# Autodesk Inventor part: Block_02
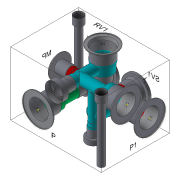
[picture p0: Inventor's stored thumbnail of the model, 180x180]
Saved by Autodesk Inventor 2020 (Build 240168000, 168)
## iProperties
Created: 2020-04
Part Number: Block_02
Material: Generico
Document SubType Name: Modeling
Designer: carlo
Density: 1 g/cm^3
Appearance: Default
DataBaseUnit: MM
VESTPrecisionDepth: 0
ActiveCavityLibraryName: *All Libraries*
VESTEnergyEfficiencyOptions: <?xml version="1.0"?> <DesignSettings xmlns:xsd="http://www.w3.org/2001/XMLSchema" xmlns:xsi="http://www.w3.org/2001/XMLSchema-instance"> <ImperialNetOptions> <
VESTUseStandardDiameter: True
VESTPrecisionLocation: 0
VESTPrecisionAngle: 0
BreakTolerance: 1,5
Author: carlo
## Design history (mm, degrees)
sketch "Schizzo1"
  geometry: L1 (0, 0)-(100, 0) reference; L2 (100, 0)-(100, -70); L3 (100, -70)-(0, -70); L4 (0, -70)-(0, 0) reference
  constraints: 8 end point, 2 horizontal, 2 parallel, 1 perpendicular, 1 vertical
  dimensions: "BlockLength" = 100 distance of L1.start L1.end; "BlockHeight" = 70 distance of L1.end L2.end
extrude "Estrusione1" join sketch "Schizzo1" distance "BlockWidth" = 75; taper "BlockTaperAngle" = 0 deg
sketch "Schizzo2"
  geometry: 1 further point
sketch "Schizzo3"
  geometry: L1 (0, 0)-(7.556, 0); L2 (0, 0)-(0, 7.556); L3 (0, 0)-(15.11, 0) reference; L4 (0, 0)-(7.556, 0); L5 (-50, 45)-(90, 45) reference
  constraints: 8 end point, 1 horizontal, 1 parallel, 1 perpendicular
  dimensions: "d6" = 0 dimension on L1.start L1.end L3.end; "d7" = 0 dimension on L1.start L4.end L3.end
revolve "P-Port" stored, may be unused: angle "d23" = 0 deg
sketch "Schizzo5"
  geometry: 1 further point
sketch "Schizzo6"
  geometry: L1 (0, 0)-(6.667, 0); L2 (0, 0)-(0, 6.667); L3 (0, 0)-(13.332, 0) reference; L4 (0, 0)-(6.667, 0); L5 (-68, -53.7)-(72, -53.7) reference
  constraints: 8 end point, 1 horizontal, 1 parallel, 1 perpendicular
  dimensions: "d26" = 0 dimension on L1.start L1.end L3.end; "d27" = 0 dimension on L1.start L4.end L3.end
revolve "RV1-CV" stored, may be unused: angle "d51" = 0 deg
sketch "Schizzo8"
  geometry: 1 further point
sketch "Schizzo9"
  geometry: L1 (0, 0)-(7.556, 0); L2 (0, 0)-(0, 7.556); L3 (0, 0)-(15.11, 0) reference; L4 (0, 0)-(7.556, 0); L5 (62, 19.31)-(-43, 19.31) reference
  constraints: 8 end point, 1 horizontal, 1 parallel, 1 perpendicular
  dimensions: "d54" = 0 dimension on L1.start L1.end L3.end; "d55" = 0 dimension on L1.start L4.end L3.end
revolve "T-Port" stored, may be unused: angle "d71" = 0 deg
sketch "Schizzo11"
  geometry: 1 further point
sketch "Schizzo12"
  geometry: L1 (0, 0)-(6.667, 0); L2 (0, 0)-(0, 6.667); L3 (0, 0)-(13.332, 0) reference; L4 (0, 0)-(6.667, 0); L5 (85, 45)-(-55, 45) reference
  constraints: 8 end point, 1 horizontal, 1 parallel, 1 perpendicular
  dimensions: "d74" = 0 dimension on L1.start L1.end L3.end; "d75" = 0 dimension on L1.start L4.end L3.end
revolve "SV1-CV" stored, may be unused: angle "d99" = 0 deg
node "Schizzo14"
sketch "Schizzo15"
  geometry: 1 further point
sketch "Schizzo16"
  geometry: L1 (0, 0)-(3.333, 0); L2 (0, 0)-(0, 3.333); L3 (0, 0)-(6.666, 0) reference; L4 (0, 0)-(3.333, 0); L5 (-85, 26)-(55, 26) reference
  constraints: 8 end point, 1 horizontal, 1 parallel, 1 perpendicular
  dimensions: "d102" = 0 dimension on L1.start L1.end L3.end; "d103" = 0 dimension on L1.start L4.end L3.end
revolve "PLUG1-Port" stored, may be unused: angle "d119" = 0 deg
node "Schizzo18"
sketch "Schizzo19"
  geometry: 1 further point
sketch "Schizzo22"
  geometry: L1 (0, 0)-(5.556, 0); L2 (0, 0)-(0, 5.556); L3 (0, 0)-(11.11, 0) reference; L4 (0, 0)-(5.556, 0); L5 (-36.3, 45)-(68.7, 45) reference
  constraints: 8 end point, 1 horizontal, 1 parallel, 1 perpendicular
  dimensions: "d142" = 0 dimension on L1.start L1.end L3.end; "d143" = 0 dimension on L1.start L4.end L3.end
revolve "MP-Port" stored, may be unused: angle "d159" = 0 deg
sketch "Schizzo24"
  geometry: 1 further point
hole "mh1-BH" sketch "Schizzo24" at (7, 68) diameter "d161" = 7; stored, may be unused: countersink angle "d165" = 90 deg, drill point angle "d167" = 120 deg; dims "d162" = 6, "d163" = 10.5, "d164" = 8, "d166" = 70
sketch "Schizzo25"
  geometry: 1 further point
hole "mh2-BH" sketch "Schizzo25" at (93, 7) diameter "d169" = 7; stored, may be unused: countersink angle "d173" = 90 deg, drill point angle "d175" = 120 deg; dims "d170" = 6, "d171" = 10.5, "d172" = 8, "d174" = 70
sketch "Schizzo26"
  geometry: 2 further points
  constraints: 1 other
  dimensions: "d282" = 23.66923 horizontal distance of point (48, 53.7) point (24.331, 65.992) (derived); "d283" = 12.29198 vertical distance of point (48, 53.7) point (24.331, 65.992) (derived)
sketch "Schizzo27"
  geometry: 2 further points
  constraints: 1 other
  dimensions: "d178" = 15 horizontal distance of point (30, -45) point (45, -64) (derived); "d179" = 19 vertical distance of point (30, -45) point (45, -64) (derived)
sketch "Schizzo28"
  geometry: 2 further points
  constraints: 1 other
  dimensions: "d180" = 18 horizontal distance of point (28, -19.31) point (46, -9) (derived); "d181" = 10.31 vertical distance of point (28, -19.31) point (46, -9) (derived)
sketch "Schizzo29"
  geometry: 2 further points
  constraints: 1 other
  dimensions: "d288" = 24.10718 horizontal distance of point (-65, -45) point (-89.107, -27.281) (derived); "d289" = 17.71872 vertical distance of point (-65, -45) point (-89.107, -27.281) (derived)
sketch "Schizzo30"
  geometry: 2 further points
  constraints: 1 other
  dimensions: "d184" = 8.7 horizontal distance of point (-53.7, -45) point (-45, -30) (derived); "d185" = 15 vertical distance of point (-53.7, -45) point (-45, -30) (derived)
sketch "Schizzo31"
  geometry: 1 further point
sketch "Schizzo32"
  geometry: L1 (0, 0)-(7.556, 0); L2 (0, 0)-(0, 7.556); L3 (0, 0)-(15.11, 0) reference; L4 (0, 0)-(7.556, 0); L5 (36.3, 45)-(-68.7, 45) reference
  constraints: 8 end point, 1 horizontal, 1 parallel, 1 perpendicular
  dimensions: "d188" = 0 dimension on L1.start L1.end L3.end; "d189" = 0 dimension on L1.start L4.end L3.end
sketch "Schizzo33"
  geometry: L1 (0, 0)-(0, 4.25); L2 (0, 4.25)-(17, 4.25); L3 (17, 4.25)-(17, 0); L4 (17, 0)-(0, 0); L5 (17, 0)-(17, -1); L6 (17, -1)-(0, -1); L7 (17, -1)-(10.5, -1); L8 (10.5, -1)-(10.5, -15.001); L9 (10.5, -15.001)-(10.5, -16); L10 (10.5, -16)-(9.55, -16); L11 (9.55, -16)-(9.55, -21); L12 (9.55, -21)-(5.5, -23.433); L13 (5.5, -23.433)-(5.5, -36); L14 (5.5, -36)-(0, -39.305); L15 (0, -39.305)-(0, 4.25)
  constraints: 30 end point, 7 parallel, 2 collinear, 1 perpendicular, 1 vertical
  dimensions: "d191" = 4.25 distance of L1.start L1.end (computed from d192, d190); "d192" = 17 distance of L1.end L2.end; "d193" = 1 distance of L3.end L5.end; "d194" = 90 deg angle of L1 L7; "d195" = 14.001 distance from line of L6 L8.end (computed from d196, d193, d197, d192, d194); "d196" = 15 distance from line of L6 L9.end; "d197" = 10.5 distance from line of L1 L9.end; "d198" = 90 deg angle of L1 L10; "d199" = 20 distance from line of L6 L11.end; "d200" = 9.55 distance from line of L1 L11.end; "d201" = 59 deg angle of L1 L12; "d202" = 36 distance from line of L4 L13.end; "d203" = 5.5 distance from line of L1 L13.end; "d204" = 59 deg angle of L1 L14
revolve "P1-Port" sketch "Schizzo33" stored, may be unused: angle "d205" = 0 deg
sketch "Schizzo38"
  geometry: 1 further point
sketch "Schizzo39"
  geometry: L1 (0, 0)-(6.667, 0); L2 (0, 0)-(0, 6.667); L3 (0, 0)-(13.332, 0) reference; L4 (0, 0)-(6.667, 0); L5 (50, 45)-(-90, 45) reference
  constraints: 8 end point, 1 horizontal, 1 parallel, 1 perpendicular
  dimensions: "d236" = 0 dimension on L1.start L1.end L3.end; "d237" = 0 dimension on L1.start L4.end L3.end
sketch "Schizzo40"
  geometry: L1 (0, 0)-(0, 3.75); L2 (0, 3.75)-(15, 3.75); L3 (15, 3.75)-(15, 0); L4 (15, 0)-(0, 0); L5 (15, 0)-(15, -3); L6 (15, -3)-(0, -3); L7 (15, -3)-(11.95, -3); L8 (11.95, -3)-(11.115, -6.116); L9 (11.115, -6.116)-(11.115, -15.735); L10 (11.115, -15.735)-(11.115, -18.01); L11 (11.115, -18.01)-(10.32, -18.01); L12 (10.32, -18.01)-(10.32, -26.866); L13 (10.32, -26.866)-(10.32, -27); L14 (10.32, -27)-(8.69, -27); L15 (8.69, -27)-(7.94, -28.299); L16 (7.94, -28.299)-(7.94, -36.295); L17 (7.94, -36.295)-(7.94, -36.3); L18 (7.94, -36.3)-(7.5, -36.564); L19 (7.5, -36.564)-(7.5, -45); L20 (7.5, -45)-(0, -49.506); L21 (0, -49.506)-(0, 3.75)
  constraints: 42 end point, 10 parallel, 2 collinear, 1 perpendicular, 1 vertical
  dimensions: "d239" = 3.75 distance of L1.start L1.end (computed from d240, d238); "d240" = 15 distance of L1.end L2.end (derived); "d241" = 3 distance of L3.end L5.end; "d242" = 90 deg angle of L1 L7; "d243" = 11.95 distance from line of L1 L7.end (derived); "d244" = 15 deg angle of L1 L8; "d245" = 12.735 distance from line of L6 L9.end (computed from d246, d241, d247, d243, d244); "d246" = 15.01 distance from line of L6 L10.end (derived); "d247" = 11.115 distance from line of L1 L10.end (derived); "d248" = 90 deg angle of L1 L11; "d249" = 23.866 distance from line of L6 L12.end (computed from d250, d246, d251, d247, d248); "d250" = 24 distance from line of L6 L13.end (derived); "d251" = 10.32 distance from line of L1 L13.end (derived); "d252" = 90 deg angle of L1 L14; "d253" = 30 deg angle of L1 L15; "d254" = 33.295 distance from line of L6 L16.end (computed from d255, d250, d256, d251, d253); "d255" = 33.3 distance from line of L6 L17.end (derived); "d256" = 7.94 distance from line of L1 L17.end (derived); "d257" = 59 deg angle of L1 L18; "d258" = 45 distance from line of L4 L19.end; "d259" = 7.5 distance from line of L1 L19.end; "d260" = 59 deg angle of L1 L20
revolve "CV1-CV" sketch "Schizzo40" stored, may be unused: angle "d261" = 0 deg
node "Schizzo41"
sketch "Schizzo42"
  geometry: 1 further point
sketch "Schizzo43"
  geometry: L1 (0, 0)-(4.444, 0); L2 (0, 0)-(0, 4.444); L3 (0, 0)-(8.888, 0) reference; L4 (0, 0)-(4.444, 0); L5 (-68, 19.31)-(72, 19.31) reference
  constraints: 8 end point, 1 horizontal, 1 parallel, 1 perpendicular
  dimensions: "d264" = 0 dimension on L1.start L1.end L3.end; "d265" = 0 dimension on L1.start L4.end L3.end
sketch "Schizzo44"
  geometry: L1 (0, 0)-(0, 2.5); L2 (0, 2.5)-(10, 2.5); L3 (10, 2.5)-(10, 0); L4 (10, 0)-(0, 0); L5 (10, 0)-(10, -6); L6 (10, -6)-(0, -6); L7 (10, -6)-(6.6, -6); L8 (6.6, -6)-(6.6, -18); L9 (6.6, -18)-(5.9, -18); L10 (5.9, -18)-(5.9, -18.003); L11 (5.9, -18.003)-(5.9, -22); L12 (5.9, -22)-(5.5, -22.24); L13 (5.5, -22.24)-(5.5, -54); L14 (5.5, -54)-(0, -57.305); L15 (0, -57.305)-(0, 2.5)
  constraints: 30 end point, 7 parallel, 2 collinear, 1 perpendicular, 1 vertical
  dimensions: "d267" = 2.5 distance of L1.start L1.end (computed from d268, d266); "d268" = 10 distance of L1.end L2.end (derived); "d269" = 6 distance of L3.end L5.end (derived); "d270" = 90 deg angle of L1 L7; "d271" = 12 distance from line of L6 L8.end (derived); "d272" = 6.6 distance from line of L1 L8.end (derived); "d273" = 90 deg angle of L1 L9; "d274" = 12.0025 distance from line of L6 L10.end (computed from d275, d271, d276, d272, d273); "d275" = 16 distance from line of L6 L11.end (derived); "d276" = 5.9 distance from line of L1 L11.end (derived); "d277" = 59 deg angle of L1 L12; "d278" = 54 distance from line of L4 L13.end (derived); "d279" = 5.5 distance from line of L1 L13.end (derived); "d280" = 59 deg angle of L1 L14
revolve "PLUG2-Port" sketch "Schizzo44" stored, may be unused: angle "d281" = 0 deg
sketch "Schizzo47"
  geometry: 2 further points
  constraints: 1 other
  dimensions: "d284" = 22.7 horizontal distance of point (53.7, -45) point (31, -65) (derived); "d285" = 20 vertical distance of point (53.7, -45) point (31, -65) (derived)
sketch "Schizzo48"
  geometry: 2 further points
  constraints: 1 other
  dimensions: "d286" = 8 horizontal distance of point (-30, -45) point (-22, -27) (derived); "d287" = 18 vertical distance of point (-30, -45) point (-22, -27) (derived)
node "Solido1"
sketch "Schizzo4"
  geometry: L1 (0, 0)-(0, 4.25); L2 (0, 4.25)-(17, 4.25); L3 (17, 4.25)-(17, 0); L4 (17, 0)-(0, 0); L5 (17, 0)-(17, -1); L6 (17, -1)-(0, -1); L7 (17, -1)-(10.5, -1); L8 (10.5, -1)-(10.5, -15.001); L9 (10.5, -15.001)-(10.5, -16); L10 (10.5, -16)-(9.55, -16); L11 (9.55, -16)-(9.55, -21); L12 (9.55, -21)-(7.5, -22.232); L13 (7.5, -22.232)-(7.5, -32); L14 (7.5, -32)-(0, -36.506); L15 (0, -36.506)-(0, 4.25)
  constraints: 30 end point, 7 parallel, 2 collinear, 1 perpendicular, 1 vertical
  dimensions: "d9" = 4.25 distance of L1.start L1.end (computed from d10, d8); "d10" = 17 distance of L1.end L2.end; "d11" = 1 distance of L3.end L5.end; "d12" = 90 deg angle of L1 L7; "d13" = 14.001 distance from line of L6 L8.end (computed from d14, d11, d15, d10, d12); "d14" = 15 distance from line of L6 L9.end; "d15" = 10.5 distance from line of L1 L9.end; "d16" = 90 deg angle of L1 L10; "d17" = 20 distance from line of L6 L11.end; "d18" = 9.55 distance from line of L1 L11.end; "d19" = 59 deg angle of L1 L12; "d20" = 32 distance from line of L4 L13.end; "d21" = 7.5 distance from line of L1 L13.end; "d22" = 59 deg angle of L1 L14
sketch "Schizzo7"
  geometry: L1 (0, 0)-(0, 3.75); L2 (0, 3.75)-(15, 3.75); L3 (15, 3.75)-(15, 0); L4 (15, 0)-(0, 0); L5 (15, 0)-(15, -1.01); L6 (15, -1.01)-(0, -1.01); L7 (15, -1.01)-(11.95, -1.01); L8 (11.95, -1.01)-(11.115, -4.126); L9 (11.115, -4.126)-(11.115, -13.745); L10 (11.115, -13.745)-(11.115, -16.02); L11 (11.115, -16.02)-(10.32, -16.02); L12 (10.32, -16.02)-(10.32, -24.876); L13 (10.32, -24.876)-(10.32, -25.01); L14 (10.32, -25.01)-(8.69, -25.01); L15 (8.69, -25.01)-(7.94, -26.309); L16 (7.94, -26.309)-(7.94, -34.305); L17 (7.94, -34.305)-(7.94, -34.31); L18 (7.94, -34.31)-(5.5, -35.776); L19 (5.5, -35.776)-(5.5, -46); L20 (5.5, -46)-(0, -49.305); L21 (0, -49.305)-(0, 3.75)
  constraints: 42 end point, 10 parallel, 2 collinear, 1 perpendicular, 1 vertical
  dimensions: "d29" = 3.75 distance of L1.start L1.end (computed from d30, d28); "d30" = 15 distance of L1.end L2.end; "d31" = 1.01 distance of L3.end L5.end; "d32" = 90 deg angle of L1 L7; "d33" = 11.95 distance from line of L1 L7.end; "d34" = 15 deg angle of L1 L8; "d35" = 12.735 distance from line of L6 L9.end (computed from d36, d31, d37, d33, d34); "d36" = 15.01 distance from line of L6 L10.end; "d37" = 11.115 distance from line of L1 L10.end; "d38" = 90 deg angle of L1 L11; "d39" = 23.866 distance from line of L6 L12.end (computed from d40, d36, d41, d37, d38); "d40" = 24 distance from line of L6 L13.end; "d41" = 10.32 distance from line of L1 L13.end; "d42" = 90 deg angle of L1 L14; "d43" = 30 deg angle of L1 L15; "d44" = 33.295 distance from line of L6 L16.end (computed from d45, d40, d46, d41, d43); "d45" = 33.3 distance from line of L6 L17.end; "d46" = 7.94 distance from line of L1 L17.end; "d47" = 59 deg angle of L1 L18; "d48" = 46 distance from line of L4 L19.end; "d49" = 5.5 distance from line of L1 L19.end; "d50" = 59 deg angle of L1 L20
sketch "Schizzo10"
  geometry: L1 (0, 0)-(0, 4.25); L2 (0, 4.25)-(17, 4.25); L3 (17, 4.25)-(17, 0); L4 (17, 0)-(0, 0); L5 (17, 0)-(17, -1); L6 (17, -1)-(0, -1); L7 (17, -1)-(10.5, -1); L8 (10.5, -1)-(10.5, -15.001); L9 (10.5, -15.001)-(10.5, -16); L10 (10.5, -16)-(9.55, -16); L11 (9.55, -16)-(9.55, -21); L12 (9.55, -21)-(5.5, -23.433); L13 (5.5, -23.433)-(5.5, -55); L14 (5.5, -55)-(0, -58.305); L15 (0, -58.305)-(0, 4.25)
  constraints: 30 end point, 7 parallel, 2 collinear, 1 perpendicular, 1 vertical
  dimensions: "d57" = 4.25 distance of L1.start L1.end (computed from d58, d56); "d58" = 17 distance of L1.end L2.end; "d59" = 1 distance of L3.end L5.end; "d60" = 90 deg angle of L1 L7; "d61" = 14.001 distance from line of L6 L8.end (computed from d62, d59, d63, d58, d60); "d62" = 15 distance from line of L6 L9.end; "d63" = 10.5 distance from line of L1 L9.end; "d64" = 90 deg angle of L1 L10; "d65" = 20 distance from line of L6 L11.end; "d66" = 9.55 distance from line of L1 L11.end; "d67" = 59 deg angle of L1 L12; "d68" = 55 distance from line of L4 L13.end; "d69" = 5.5 distance from line of L1 L13.end; "d70" = 59 deg angle of L1 L14
sketch "Schizzo13"
  geometry: L1 (0, 0)-(0, 3.75); L2 (0, 3.75)-(15, 3.75); L3 (15, 3.75)-(15, 0); L4 (15, 0)-(0, 0); L5 (15, 0)-(15, -3); L6 (15, -3)-(0, -3); L7 (15, -3)-(11.95, -3); L8 (11.95, -3)-(11.115, -6.116); L9 (11.115, -6.116)-(11.115, -15.735); L10 (11.115, -15.735)-(11.115, -18.01); L11 (11.115, -18.01)-(10.32, -18.01); L12 (10.32, -18.01)-(10.32, -26.866); L13 (10.32, -26.866)-(10.32, -27); L14 (10.32, -27)-(8.69, -27); L15 (8.69, -27)-(7.94, -28.299); L16 (7.94, -28.299)-(7.94, -36.295); L17 (7.94, -36.295)-(7.94, -36.3); L18 (7.94, -36.3)-(7.5, -36.564); L19 (7.5, -36.564)-(7.5, -49); L20 (7.5, -49)-(0, -53.506); L21 (0, -53.506)-(0, 3.75)
  constraints: 42 end point, 10 parallel, 2 collinear, 1 perpendicular, 1 vertical
  dimensions: "d77" = 3.75 distance of L1.start L1.end (computed from d78, d76); "d78" = 15 distance of L1.end L2.end; "d79" = 3 distance of L3.end L5.end; "d80" = 90 deg angle of L1 L7; "d81" = 11.95 distance from line of L1 L7.end; "d82" = 15 deg angle of L1 L8; "d83" = 12.735 distance from line of L6 L9.end (computed from d84, d79, d85, d81, d82); "d84" = 15.01 distance from line of L6 L10.end; "d85" = 11.115 distance from line of L1 L10.end; "d86" = 90 deg angle of L1 L11; "d87" = 23.866 distance from line of L6 L12.end (computed from d88, d84, d89, d85, d86); "d88" = 24 distance from line of L6 L13.end; "d89" = 10.32 distance from line of L1 L13.end; "d90" = 90 deg angle of L1 L14; "d91" = 30 deg angle of L1 L15; "d92" = 33.295 distance from line of L6 L16.end (computed from d93, d88, d94, d89, d91); "d93" = 33.3 distance from line of L6 L17.end; "d94" = 7.94 distance from line of L1 L17.end; "d95" = 59 deg angle of L1 L18; "d96" = 49 distance from line of L4 L19.end; "d97" = 7.5 distance from line of L1 L19.end; "d98" = 59 deg angle of L1 L20
sketch "Schizzo17"
  geometry: L1 (0, 0)-(0, 1.875); L2 (0, 1.875)-(7.5, 1.875); L3 (7.5, 1.875)-(7.5, 0); L4 (7.5, 0)-(0, 0); L5 (7.5, 0)-(7.5, -5); L6 (7.5, -5)-(0, -5); L7 (7.5, -5)-(4.9, -5); L8 (4.9, -5)-(4.9, -13.251); L9 (4.9, -13.251)-(4.9, -15); L10 (4.9, -15)-(4.4, -15); L11 (4.4, -15)-(4.4, -19); L12 (4.4, -19)-(4.25, -19.09); L13 (4.25, -19.09)-(4.25, -49); L14 (4.25, -49)-(0, -51.554); L15 (0, -51.554)-(0, 1.875)
  constraints: 30 end point, 7 parallel, 2 collinear, 1 perpendicular, 1 vertical
  dimensions: "d105" = 1.875 distance of L1.start L1.end (computed from d106, d104); "d106" = 7.5 distance of L1.end L2.end; "d107" = 5 distance of L3.end L5.end; "d108" = 90 deg angle of L1 L7; "d109" = 8.251 distance from line of L6 L8.end (computed from d110, d107, d111, d106, d108); "d110" = 10 distance from line of L6 L9.end; "d111" = 4.9 distance from line of L1 L9.end; "d112" = 90 deg angle of L1 L10; "d113" = 14 distance from line of L6 L11.end; "d114" = 4.4 distance from line of L1 L11.end; "d115" = 59 deg angle of L1 L12; "d116" = 49 distance from line of L4 L13.end; "d117" = 4.25 distance from line of L1 L13.end; "d118" = 59 deg angle of L1 L14
sketch "Schizzo23"
  geometry: L1 (0, 0)-(0, 3.125); L2 (0, 3.125)-(12.5, 3.125); L3 (12.5, 3.125)-(12.5, 0); L4 (12.5, 0)-(0, 0); L5 (12.5, 0)-(12.5, -1); L6 (12.5, -1)-(0, -1); L7 (12.5, -1)-(6.6, -1); L8 (6.6, -1)-(6.6, -13); L9 (6.6, -13)-(5.9, -13); L10 (5.9, -13)-(5.9, -13.003); L11 (5.9, -13.003)-(5.9, -17); L12 (5.9, -17)-(5.5, -17.24); L13 (5.5, -17.24)-(5.5, -76.115); L14 (5.5, -76.115)-(0, -79.42); L15 (0, -79.42)-(0, 3.125)
  constraints: 30 end point, 7 parallel, 2 collinear, 1 perpendicular, 1 vertical
  dimensions: "d145" = 3.125 distance of L1.start L1.end (computed from d146, d144); "d146" = 12.5 distance of L1.end L2.end; "d147" = 1 distance of L3.end L5.end; "d148" = 90 deg angle of L1 L7; "d149" = 12 distance from line of L6 L8.end; "d150" = 6.6 distance from line of L1 L8.end; "d151" = 90 deg angle of L1 L9; "d152" = 12.0025 distance from line of L6 L10.end (computed from d153, d149, d154, d150, d151); "d153" = 16 distance from line of L6 L11.end; "d154" = 5.9 distance from line of L1 L11.end; "d155" = 59 deg angle of L1 L12; "d156" = 76.115 distance from line of L4 L13.end; "d157" = 5.5 distance from line of L1 L13.end; "d158" = 59 deg angle of L1 L14
other parameters: "d4" = 0, "d5" = 0, "d8" = 90 deg, "d24" = 0, "d25" = 0, "d28" = 90 deg, "d52" = 0, "d53" = 0, "d56" = 90 deg, "d72" = 0, "d73" = 0, "d76" = 90 deg, "d100" = 0, "d101" = 0, "d104" = 90 deg, "d120" = 0, "d140" = 0, "d141" = 0, "d144" = 90 deg, "d160" = 0, "d168" = 0, "d176" = 12 (derived), "d177" = 17 (derived), "d182" = 12 (derived), "d183" = 17 (derived), "d186" = 0, "d187" = 0, "d190" = 90 deg, "d234" = 0, "d235" = 0, "d238" = 90 deg, "d262" = 0, "d263" = 0, "d266" = 90 deg
